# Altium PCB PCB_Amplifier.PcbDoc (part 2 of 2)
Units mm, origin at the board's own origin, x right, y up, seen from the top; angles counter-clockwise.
Board outline 88.51 x 102.08 mm, 4 copper layers (Top Layer, GND, VDD, Bottom Layer); 234 components, 166 nets, 733 pads, 363 vias.
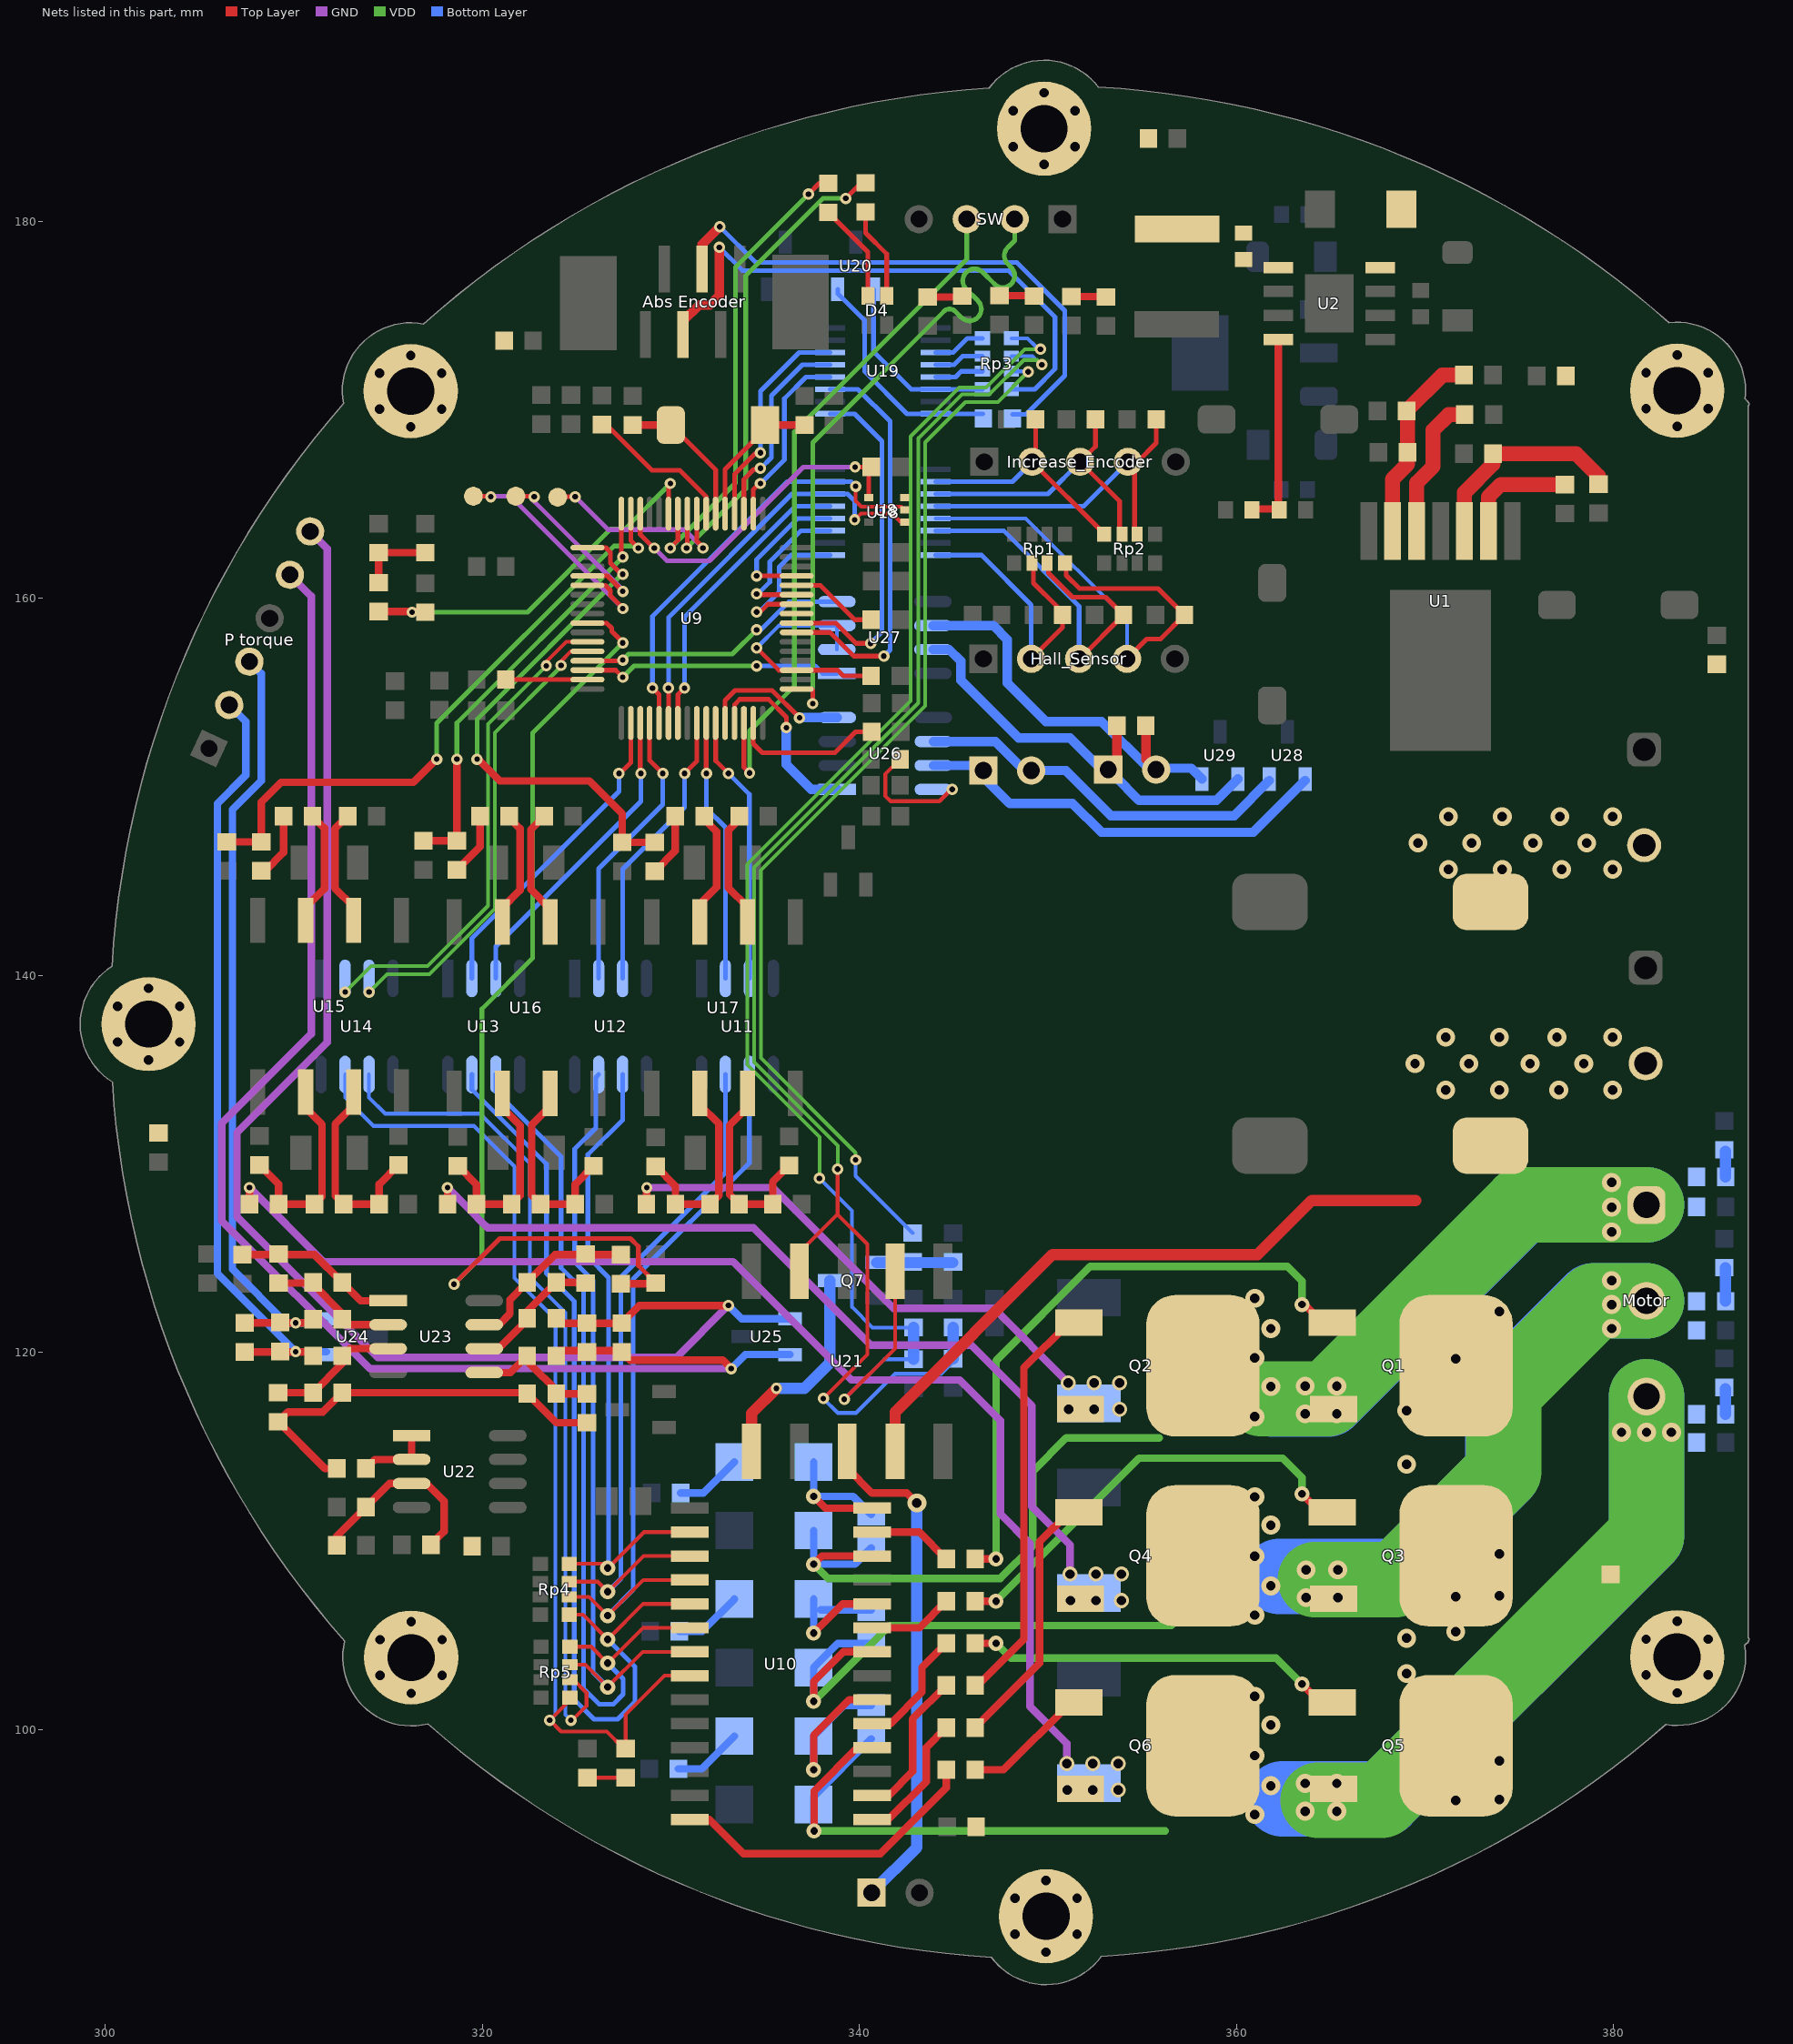
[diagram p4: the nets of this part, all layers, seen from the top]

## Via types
v1: diameter 0.6, hole 0.3, Top Layer to Bottom Layer, 150 vias
v2: diameter 1, hole 0.5, Top Layer to Bottom Layer, 134 vias
v3: diameter 0.8, hole 0.5, Top Layer to Bottom Layer, 60 vias
v4: diameter 0.8, hole 0.4, Top Layer to Bottom Layer, 19 vias

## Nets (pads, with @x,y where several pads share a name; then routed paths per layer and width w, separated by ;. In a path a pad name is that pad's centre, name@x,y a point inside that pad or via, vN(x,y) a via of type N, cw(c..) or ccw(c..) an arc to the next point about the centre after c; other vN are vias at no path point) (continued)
ADC12_IN15: C88.2 R99.2 U9.25 | length 55
  Top Layer w0.25: v1(318.5,123.625) 320.925,126.05 327.853,126.05 328.275,125.628 328.275,124.615 C88.2@329.2,123.69 ; U9.25@325.575,158.7 326.593,158.7 326.865,158.428 326.865,158.26 v1@327.325,157.8
  Top Layer w0.4: R99.2@327.35,123.655 C88.2@329.165,123.655
  VDD w0.25: v1(318.5,123.625) 319.975,125.1 319.975,138.225 322.675,140.925 322.675,152.871 v1(327.45,157.646)
ADC123_IN1: C35.2 R38.2 U9.15 | length 32.8
  Top Layer w0.25: U9.15@327.875,164.5 327.875,163.075 v1(328.275,162.675)
  Top Layer w0.4: C35.2@306.45,147.095 R38.2@308.275,147.095 308.275,149.2 309.325,150.25 316.35,150.25 v1@317.638,151.537
  VDD w0.25: v1(317.581,151.475) 317.581,153.381 326.985,162.785 328.165,162.785 v1(328.275,162.675)
ADC123_IN2: C45.2 R48.2 U9.16 | length 22.8
  Top Layer w0.25: U9.16@327.375,164.5 327.375,162.3 v1@327.475,162.2
  Top Layer w0.4: C45.2@316.875,147.145 R48.2@318.65,147.145 v1(318.65,151.475)
  VDD w0.25: v1(318.65,151.475) 318.65,153.4 v1(327.45,162.2)
ADC123_IN3: C55.2 R58.2 U9.17 | length 27.9
  Top Layer w0.25: U9.17@325.575,162.7 326.55,162.7 326.8,162.45 326.8,161.875 v1@327.45,161.225
  Top Layer w0.4: v1@319.775,151.475 320.925,150.325 325.675,150.325 327.425,148.575 C55.2@327.425,147.07 R58.2@329.15,147.07
  VDD w0.25: v1(319.719,151.475) 319.719,153.588 327.356,161.225 v1@327.45,161.225
  other v1: 327.45,161.289
ADC123_IN13: C79.2 R103.1 U9.11 | length 20.6
  Top Layer w0.25: U9.11@329.875,164.5 v1@329.875,166.1
  Top Layer w0.4: R103.1@314.5,159.305 C79.2@316.94,159.305
  VDD w0.25: v1(316.275,159.275) 322.4,159.275 326.8,163.675 327.55,163.675 v1(329.975,166.1)
BRAKE_INPUT_SIG: R71.1 Rp3.7 | length 56.9
  VDD w0.2: v1(339.8,130.225) 339.8,130.6 334.775,135.625 334.775,145.6 343.485,154.31 343.485,168.285 345.625,170.425 347.35,170.425 v1(348.95,172.025)
  Bottom Layer w0.2: v1(339.8,130.225) 339.8,129.37 R71.1@342.825,126.345 ; Rp3.7@348.07,172.05 v1@348.925,172.05 ; v1@348.95,172.05 v1@349.075,172.05
CLOSE_SIG: C151.2 R72.1 Rp3.6 U21.9 | length 81.7
  Top Layer w0.2: U21.9@336.815,124.325 336.815,125.315 338.825,127.325 ; v1(338.088,117.563) 340.425,119.9 340.425,125.75 338.838,127.337 ; 338.842,127.337 v1(338.842,129.733)
  VDD w0.2: v1@338.85,129.733 338.85,130.975 334.415,135.41 334.415,145.749 343.125,154.459 343.125,168.5 345.45,170.825 346.9,170.825 348.725,172.65 349.425,172.65 v1(349.675,172.4)
  Bottom Layer w0.2: v1(338.088,117.563) 338.85,116.8 339.825,116.8 341.9,118.875 344.33,118.875 C151.2@344.975,119.52 ; Rp3.6@348.07,172.85 349.175,172.85 v1@349.45,172.575
  Bottom Layer w0.6: C151.2@344.975,119.67 R72.1@344.975,121.33
D_GND: U8.3
DAC_OUT1: tp1.1 U9.20 | length 10.2
  Top Layer w0.25: tp1.1@321.912,165.425 v1@322.75,165.425 ; U9.20@325.575,161.2 326.625,161.2 327.35,160.475 v1@327.35,160.3
  GND w0.25: v1@322.75,165.425 322.75,165.15 327.45,160.45 v1@327.45,160.225
  other v1: 327.45,160.379 322.75,165.4
DAC_OUT2: tp2.1 U9.21 | length 13
  Top Layer w0.25: tp2.1@319.5,165.425 v1@320.45,165.425 ; U9.21@325.575,160.7 326.525,160.7 326.8,160.425 326.8,160.15 v1@327.45,159.5
  GND w0.25: v1@320.45,165.425 321.5,165.425 327.341,159.584 v1@327.341,159.359
  other v1: 327.45,159.468 320.45,165.4
DRIVE_H1: R20.1 U10.27 | length 4.5
  Top Layer w0.4: U10.27@340.675,110.48 343.175,110.48 R20.1@344.605,109.05
DRIVE_H2: R22.1 U10.23 | length 4.5
  Top Layer w0.4: U10.23@340.675,105.4 343.19,105.4 R22.1@344.605,106.815
DRIVE_H3: R24.1 U10.19 | length 6.5
  Top Layer w0.4: U10.19@340.675,100.32 341.645,100.32 343.325,102 343.325,103.3 R24.1@344.605,104.58
DRIVE_L1: R21.1 U10.16 | length 8
  Top Layer w0.4: U10.16@340.675,96.51 341.56,96.51 342.825,97.775 342.825,100.565 R21.1@344.605,102.345
DRIVE_L2: R23.1 U10.15 | length 7
  Top Layer w0.4: U10.15@340.675,95.24 341.54,95.24 343.55,97.25 343.55,99.055 R23.1@344.605,100.11
DRIVE_L3: R25.1 U10.14 | length 16.8
  Top Layer w0.4: U10.14@331,95.24 332.035,95.24 333.85,93.425 341.125,93.425 344.605,96.905 R25.1@344.605,97.875
EN: Rp5.2 U14.6 | length 44.6
  Top Layer w0.2: Rp5.2@324.645,102.65 324.838,102.65 325.525,101.963 325.525,101.25 324.775,100.5 v1(324.7,100.5)
  Bottom Layer w0.2: U14.6@313.99,134.75 313.99,133.535 314.85,132.675 319.875,132.675 322.525,130.025 322.525,124 324.4,122.125 324.4,100.8 v1(324.7,100.5)
FAULT: R60.2 Rp5.1 U10.8 U14.7 | length 54.1
  Top Layer w0.2: Rp5.1@324.645,101.57 v1(323.575,100.5) 324.175,99.9 326.6,99.9 327.505,98.995 R60.2@327.6,98.995 ; R60.2@327.6,99.27 327.6,100.8 329.66,102.86 U10.8@331,102.86
  Bottom Layer w0.2: U14.7@312.72,134.75 312.72,133.53 314.225,132.025 319.55,132.025 321.7,129.875 321.7,123.95 323.885,121.765 323.885,119.457 323.875,119.447 323.875,100.8 v1(323.575,100.5)
HIN1: Rp4.4 U10.2 U12.6 | length 34.6
  Top Layer w0.2: Rp4.4@324.62,108.8 326.425,108.8 v4(326.65,108.575) 326.675,108.575 328.58,110.48 U10.2@331,110.48
  Bottom Layer w0.25: v4@326.7,108.625 326.7,123.975 325.6,125.075 325.6,130.5 327.44,132.34 U12.6@327.44,134.75
HIN2: Rp4.3 U10.3 U11.7 | length 37.4
  Top Layer w0.2: Rp4.3@324.62,107.85 326.112,107.85 v4(326.65,107.313) 328.547,109.21 U10.3@331,109.21
  Bottom Layer w0.25: v4(326.65,107.313) 327.35,108.013 327.35,124 332.895,129.545 U11.7@332.895,134.75
HIN3: Rp4.2 U10.4 U11.6 | length 39.4
  Top Layer w0.2: Rp4.2@324.62,107.05 325.65,107.05 v4(326.65,106.05) 328.54,107.94 U10.4@331,107.94
  Bottom Layer w0.25: v4@326.638,106.063 328,107.425 328,123.9 334.165,130.065 U11.6@334.165,134.75
LIN1: Rp4.1 U10.5 U13.7 | length 51.1
  Top Layer w0.2: Rp4.1@324.62,106.1 325.337,106.1 v4(326.65,104.788) 328.532,106.67 U10.5@331,106.67
  Bottom Layer w0.25: U13.7@319.445,134.75 319.445,133.955 323.4,130 323.4,124.2 324.875,122.725 324.875,101.6 325.925,100.55 327.175,100.55 328.1,101.475 328.1,103.338 v4(326.65,104.788)
LIN2: Rp5.4 U10.6 U13.6 | length 46.7
  Top Layer w0.2: Rp5.4@324.645,104.4 325.775,104.4 v4(326.65,103.525) 328.525,105.4 U10.6@331,105.4
  Bottom Layer w0.25: U13.6@320.715,134.75 320.715,133.86 324.175,130.4 324.175,124.5 325.375,123.3 325.375,102.175 326.2,101.35 326.95,101.35 327.475,101.875 327.475,102.7 v4(326.65,103.525)
LIN3: Rp5.3 U10.7 U12.7 | length 41.4
  Top Layer w0.2: Rp5.3@324.645,103.45 325.462,103.45 v4(326.65,102.263) ; v4@326.65,102.275 328.505,104.13 U10.7@331,104.13
  Bottom Layer w0.25: U12.7@326.17,134.75 326.015,134.595 326.015,131.915 324.9,130.8 324.9,124.8 325.875,123.825 325.875,103.038 v4(326.65,102.263)
NetBrake_1: Brake.1 U21.3 | length 27
  Top Layer w0.4: U21.3@339.355,114.765 339.355,113.87 340.675,112.55 342.525,112.55 v2(343.05,112.025)
  Bottom Layer w0.6: Brake.1@340.65,91.35 343.05,93.75 v2(343.05,112.025)
NetC1_2: C1.2 U9.47 | length 8
  Top Layer w0.25: U9.47@334.375,153.4 334.375,152.3 334.85,151.825 338.7,151.825 339.8,152.925 C1.2@340.655,152.925
NetC2_2: C2.2 U9.31 | length 4.3
  Top Layer w0.25: C2.2@321.245,155.7 U9.31@325.575,155.7
NetC3_1: C3.1 U9.7 | length 8
  Top Layer w0.25: C3.1@326.35,169.23 326.57,169.23 329,166.8 330.475,166.8 331.875,165.4 U9.7@331.875,164.5
NetC4_1: C4.1 U9.6 Y1.1 | length 7.5
  Top Layer w0.25: Y1.1@330,169.2 332.375,166.825 U9.6@332.375,164.5
  Top Layer w0.4: C4.1@328.18,169.2 Y1.1@330,169.2
NetC5_1: C5.1 U9.5 Y1.2 | length 7.3
  Top Layer w0.2: C5.1@336.895,169.2 C5.1@336.9,169.205
  Top Layer w0.25: U9.5@332.875,164.5 332.875,166.85 Y1.2@335,168.975
  Top Layer w0.4: Y1.2@335,169.2 C5.1@336.895,169.2
NetC21_1: C21.1 D5.2 U10.28 | length 8.6
  Top Layer w0.4: v4(337.575,112.375) 338.2,111.75 U10.28@340.675,111.75
  Bottom Layer w0.4: D5.2@337.575,114.2 v4(337.575,112.375) 339.665,112.375 C21.1@340.625,111.415
NetC22_1: C22.1 D7.2 U10.24 | length 8.2
  Top Layer w0.4: v4(337.575,105.125) 339.12,106.67 U10.24@340.675,106.67
  Bottom Layer w0.4: v4(337.575,105.125) D7.2@337.575,106.93 ; D7.2@337.948,106.353 C22.1@340.625,106.353
NetC23_1: C23.1 D9.2 U10.20 | length 11.2
  Top Layer w0.4: v4(337.575,97.875) 337.575,99.7 339.465,101.59 U10.20@340.675,101.59
  Bottom Layer w0.4: v4(337.575,97.875) D9.2@337.575,99.66 339.205,101.29 C23.1@340.625,101.29
NetC31_1: C31.1 C32.2 R35.2 U15.3 | length 10.2
  Top Layer w0.4: U15.3@313.17,133.095 312.2,132.125 312.2,128.32 C31.1@312.645,127.875 R35.2@314.53,127.875 314.53,128.935 C32.2@315.55,129.955
NetC31_2: C31.2 C33.2 R34.2 U15.2 | length 10
  Top Layer w0.4: C33.2@308.175,129.955 309.195,128.935 R34.2@309.195,127.875 C31.2@311.105,127.875 311.5,128.27 311.5,132.1 U15.2@310.63,132.97
NetC41_1: C41.1 C42.2 R45.2 U16.3 | length 10
  Top Layer w0.4: U16.3@323.595,133.045 322.625,132.075 322.625,128.345 C41.1@323.095,127.875 R45.2@324.93,127.875 324.93,128.935 C42.2@325.9,129.905
NetC41_2: C41.2 C43.2 R44.2 U16.2 | length 10
  Top Layer w0.4: C43.2@318.7,129.905 319.695,128.91 R44.2@319.695,127.875 C41.2@321.555,127.875 322,128.32 322,132.05 U16.2@321.055,132.995
NetC51_1: C51.1 C52.2 R55.2 U17.3 | length 10
  Top Layer w0.4: U17.3@334.07,133.02 333.11,132.06 333.11,128.385 C51.1@333.62,127.875 R55.2@335.405,127.875 335.405,129.06 C52.2@336.275,129.93
NetC51_2: C51.2 C53.2 R54.2 U17.2 | length 10.2
  Top Layer w0.4: C53.2@329.2,129.88 330.245,128.835 R54.2@330.245,127.875 C51.2@332.08,127.875 332.55,128.345 332.55,132.125 U17.2@331.53,133.145
NetC62_2: C62.2 Hall_Sensor.2 Rp1.2 U18.16 | length 14.9
  Top Layer w0.25: Hall_Sensor.2@349.115,156.8 350.778,158.463 C62.2@350.778,159.125 ; Rp1.2@349.225,161.88 349.225,160.825 C62.2@350.478,159.572
  Bottom Layer w0.25: U18.16@344.05,162.3 346.475,162.3 349.115,159.66 Hall_Sensor.2@349.115,156.8
NetC63_2: C63.2 Hall_Sensor.3 Rp1.3 U18.14 | length 20.8
  Top Layer w0.25: Rp1.3@350.025,161.88 350.025,161.35 351.3,160.075 353.062,160.075 C63.2@354.012,159.125 351.687,156.8 Hall_Sensor.3@351.655,156.8
  Bottom Layer w0.25: U18.14@344.05,163.6 347.65,163.6 351.655,159.595 Hall_Sensor.3@351.655,156.8
NetC64_2: C64.2 Hall_Sensor.4 Rp1.4 U18.13 | length 26.3
  Top Layer w0.25: Rp1.4@350.975,161.88 350.975,161.225 351.675,160.525 355.845,160.525 C64.2@357.245,159.125 355.97,157.85 355.245,157.85 Hall_Sensor.4@354.195,156.8
  Bottom Layer w0.2: U18.13@344.05,164.25 348.825,164.25 354.195,158.88 Hall_Sensor.4@354.195,156.8
NetC65_2: C65.2 Increase_Encoder.2 Rp2.4 U18.10 | length 13
  Top Layer w0.25: Increase_Encoder.2@349.165,167.25 352.85,163.565 Rp2.4@352.85,163.42 ; Increase_Encoder.2@349.345,167.43 C65.2@349.345,169.5
  Bottom Layer w0.25: U18.10@344.05,166.2 348.115,166.2 Increase_Encoder.2@349.165,167.25
NetC66_2: C66.2 Increase_Encoder.3 Rp2.3 U18.11 | length 15.6
  Top Layer w0.25: C66.2@352.52,169.5 352.52,168.065 Increase_Encoder.3@351.705,167.25 353.8,165.155 Rp2.3@353.8,163.42
  Bottom Layer w0.25: U18.11@344.05,165.55 350.005,165.55 Increase_Encoder.3@351.705,167.25
NetC67_2: C67.2 Increase_Encoder.4 Rp2.2 U18.12 | length 17.3
  Top Layer w0.25: Rp2.2@354.6,163.42 Increase_Encoder.4@354.6,166.895 ; Increase_Encoder.4@354.75,167.25 355.745,168.245 C67.2@355.745,169.5
  Bottom Layer w0.25: U18.12@344.05,164.9 351.895,164.9 Increase_Encoder.4@354.245,167.25
NetC72_1: C72.1 L1.2 T1.2 U2.8
NetC72_2: C72.2 U2.1
NetC80_2: C80.2 R85.1 R86.2 U22.3 | length 10.3
  Top Layer w0.4: R86.2@312.28,109.775 312.28,110.26 R85.1@313.82,111.8 315.08,113.06 U22.3@316.25,113.06 317.04,113.06 317.975,112.125 317.975,110.505 C80.2@317.27,109.8
NetC82_2: C82.2 R90.2 R91.2 U23.3 | length 6.1
  Top Layer w0.4: C82.2@309.175,117.87 311.025,117.87 R91.2@311.03,117.875 R90.2@312.57,119.415 ; R90.2@312.955,120.21 U23.3@315,120.21
NetC83_1: C83.1 R89.2 R92.1 U23.2 | length 6.2
  Top Layer w0.4: C83.1@309.2,123.69 310.995,123.69 310.995,123.655 R89.2@312.57,122.08 ; R89.2@312.865,121.48 U23.2@315,121.48
NetC83_2: C83.2 R92.2 R93.1 U23.1 | length 8.7
  Top Layer w0.4: R93.1@307.275,125.195 311.1,125.195 R92.2@312.57,123.725 313.545,122.75 U23.1@315,122.75
NetC86_1: C86.1 R95.1 R96.1 U23.5 | length 6.8
  Top Layer w0.4: U23.5@320.1,118.94 321.495,118.94 R95.1@322.38,119.825 322.38,119.545 324.105,117.82 C86.1@325.55,117.82
NetC87_1: C87.1 R94.1 R97.1 U23.6 | length 7.1
  Top Layer w0.4: U23.6@320.1,120.21 320.86,120.21 322.38,121.73 R94.1@322.38,121.825 322.38,122.185 R97.1@323.92,123.725 325.44,123.725 C87.1@325.475,123.69
NetC87_2: C87.2 R97.2 R99.1 U23.7 | length 9.2
  Top Layer w0.4: U23.7@320.1,121.48 320.88,121.48 321.46,122.06 321.46,122.805 R97.2@322.38,123.725 323.85,125.195 R99.1@327.35,125.195
NetC91_2: C91.2 MH1.1
  other v3: 383.375,169.125 381.73,170.075 385.02,170.075 381.73,171.975 385.02,171.975 383.375,172.925
NetC92_2: C92.2 MH2.1
  other v3: 349.8,183.025 348.155,183.975 351.445,183.975 348.155,185.875 351.445,185.875 349.8,186.825
NetC93_2: C93.2 MH3.1
  other v3: 316.2,169.1 314.555,170.05 317.845,170.05 314.555,171.95 317.845,171.95 316.2,172.9
NetC94_2: C94.2 MH4.1
  other v3: 302.3,135.525 300.655,136.475 303.945,136.475 300.655,138.375 303.945,138.375 302.3,139.325
NetC95_2: C95.2 MH5.1
  other v3: 316.225,101.925 314.58,102.875 317.87,102.875 314.58,104.775 317.87,104.775 316.225,105.725
NetC96_2: C96.2 MH6.1
  other v3: 349.9,88.2 348.255,89.15 351.545,89.15 348.255,91.05 351.545,91.05 349.9,92
NetC97_2: C97.2 MH7.1
  other v3: 383.375,101.95 381.73,102.9 385.02,102.9 381.73,104.8 385.02,104.8 383.375,105.75
NetCff_1: Cff.1 Rfbb.2 Rfbt.1 U1.6 | length 10.5
  Top Layer w0.8: U1.6@368.285,163.575 368.285,166.335 369.07,167.12 Rfbt.1@369.07,167.75 369.07,170 370.92,171.85 Rfbb.2@372.07,171.85
NetCo1_1: Co1.1 R31.2 | length 1.4
  Bottom Layer w0.6: Co1.1@385.945,129.325 R31.2@385.945,130.685
NetCo3_1: Co3.1 R32.2 | length 1.8
  Bottom Layer w0.6: Co3.1@385.945,122.725 R32.2@385.945,124.5
NetCo5_1: Co5.1 R33.2 | length 1.3
  Bottom Layer w0.6: Co5.1@385.945,116.725 R33.2@385.945,118.075
NetCss_2: Css.2 U1.5 | length 7.7
  Top Layer w0.8: U1.5@369.555,163.575 369.555,166.13 370.425,167 370.425,168.925 371.25,169.75 Css.2@372.105,169.75
NetD1_A: D1.A R77.1 | length 1.8
  Top Layer w0.4: D1.A@351.247,176.02 R77.1@353.05,176.02
NetD2_A: D2.A R78.1 | length 1.8
  Top Layer w0.4: D2.A@347.436,176.07 R78.1@349.239,176.07
NetD3_A: D3.A R79.1 | length 1.8
  Top Layer w0.4: D3.A@343.625,175.995 R79.1@345.403,175.995
NetD4_1: D4.1 R100.1 | length 4.9
  Top Layer w0.25: R100.1@340.325,180.505 340.325,179.4 341.45,178.275 D4.1@341.45,176.05
NetD4_2: D4.2 R104.1 | length 5.3
  Top Layer w0.25: R104.1@338.35,180.48 340.45,178.38 D4.2@340.45,176.05
NetD5_1: D5.1 R12.2 | length 3.5
  Bottom Layer w0.4: R12.2@330.52,112.55 331.725,112.55 D5.1@333.375,114.2
NetD7_1: D7.1 R13.2 | length 3.6
  Bottom Layer w0.4: R13.2@330.445,105.225 331.67,105.225 D7.1@333.375,106.93
NetD9_1: D9.1 R14.2 | length 3.7
  Bottom Layer w0.4: R14.2@330.395,97.925 331.64,97.925 D9.1@333.375,99.66
NetD11_K: D11.K R60.1 | length 2
  Top Layer w0.2: D11.K@325.575,97.455 R60.1@327.6,97.455
NetP485_1: P485.1 R4.1 U27.7 U29.1 | length 22.4
  Top Layer w0.5: P485.1@353.655,151.38 R4.1@353.655,153.25
  Bottom Layer w0.5: U27.7@343.9,157.295 344.755,157.295 345.375,156.675 345.375,155.675 348.45,152.6 351.175,152.6 353.2,150.575 353.55,150.575 354.825,149.3 358.95,149.3 U29.1@360.075,150.425
NetP485_2: P485.2 R4.2 U27.6 U29.2 | length 21.5
  Top Layer w0.5: R4.2@355.195,153.25 355.195,151.47 P485.2@355.74,150.925
  Bottom Layer w0.5: U27.6@343.9,158.565 347.11,158.565 347.85,157.825 347.85,155.525 349.9,153.475 352.84,153.475 355.315,151 357.6,151 U29.2@358.175,150.425
NetPcan_1: Pcan.1 U26.7 U28.1 | length 22.3
  Bottom Layer w0.5: U26.7@343.925,151.145 345.955,151.145 346.575,150.525 347.975,149.125 351.305,149.125 352.83,147.6 360.9,147.6 U28.1@363.65,150.35
NetPcan_2: Pcan.2 U26.6 U28.2 | length 20.2
  Bottom Layer w0.5: U26.6@343.925,152.415 347.225,152.415 348.765,150.875 350.95,150.875 353.35,148.475 359.875,148.475 U28.2@361.75,150.35
NetQ1_1: Q1.1 R20.2 | length 33.4
  Top Layer w0.4: R20.2@346.145,109.05 v4(347.25,109.05) ; v4@363.6,122.55 364.55,121.6 Q1.1@365.075,121.6
  VDD w0.4: v4(347.25,109.05) 347.25,119.575 352.25,124.575 362.7,124.575 363.475,123.8 v4(363.475,122.55)
NetQ2_1: Q2.1 R21.2 | length 21.4
  Top Layer w0.4: R21.2@346.145,102.345 346.27,102.345 348.725,104.8 348.725,119.2 Q2.1@351.125,121.6
NetQ3_1: Q3.1 R22.2 | length 23.8
  Top Layer w0.4: R22.2@346.145,106.815 v4(347.25,106.815) ; v4@363.5,112.5 364.475,111.525 Q3.1@365.075,111.525
  VDD w0.4: v4(347.25,106.815) 354.835,114.4 362.45,114.4 363.475,113.375 v4(363.475,112.5)
NetQ4_1: Q4.1 R23.2 | length 13.5
  Top Layer w0.4: R23.2@346.145,100.11 349.55,103.515 349.55,109.95 Q4.1@351.125,111.525
NetQ5_1: Q5.1 R24.2 | length 20.3
  Top Layer w0.4: R24.2@346.145,104.58 v4(347.25,104.58) v4@347.305,104.58 ; v4(363.475,102.425) 364.45,101.45 Q5.1@365.075,101.45
  VDD w0.4: v4(347.25,104.58) 348.03,103.8 362.1,103.8 v4(363.475,102.425)
NetQ6_1: Q6.1 R25.2 | length 6.6
  Top Layer w0.4: R25.2@346.145,97.875 347.65,97.875 Q6.1@351.225,101.45
NetQ7_1: Q7.1 R70.1 R71.2 | length 4
  Bottom Layer w0.6: Q7.1@340.925,124.775 R70.1@344.945,124.775
NetQ7_3: Q7.3 U21.1 | length 11.6
  Top Layer w0.6: U21.1@334.275,114.765 334.275,116.775 v1(335.6,118.1)
  Bottom Layer w0.6: v1(335.6,118.1) 337.075,118.1 338.425,119.45 Q7.3@338.425,123.825
NetR1_2: R1.2 U9.60 | length 4.8
  Top Layer w0.25: U9.60@336.675,160.7 337.925,160.7 339.75,158.875 R1.2@340.68,158.875
NetR5_1: R5.1 U26.8 | length 6.3
  Top Layer w0.2: R5.1@342.16,151.475 341.375,150.69 341.375,149.525 341.65,149.25 344.25,149.25 344.925,149.925 v1(344.925,149.875)
NetR36_1: R36.1 U15.7 | length 5.5
  Top Layer w0.4: U15.7@310.63,143.605 311.625,144.6 311.625,147.82 R36.1@310.995,148.45
NetR36_2: R36.2 R38.1 | length 3.5
  Top Layer w0.4: R38.1@308.275,145.555 308.48,145.555 309.455,146.53 R36.2@309.455,148.45
NetR37_1: R37.1 U15.6 | length 5.5
  Top Layer w0.4: R37.1@312.855,148.45 312.185,147.78 312.185,144.64 U15.6@313.17,143.655
NetR46_1: R46.1 U16.7 | length 5.5
  Top Layer w0.4: U16.7@321.055,143.58 322,144.525 322,147.8 321.42,148.38 R46.1@321.42,148.45
NetR46_2: R46.2 R48.1 | length 3.4
  Top Layer w0.4: R48.1@318.65,145.605 319.88,146.835 R46.2@319.88,148.45
NetR47_1: R47.1 U16.6 | length 5.6
  Top Layer w0.4: R47.1@323.28,148.45 322.575,147.745 322.575,144.575 U16.6@323.595,143.555
NetR56_1: R56.1 U17.7 | length 5.3
  Top Layer w0.4: U17.7@331.53,143.78 332.425,144.675 332.425,147.65 331.77,148.305 R56.1@331.77,148.45
NetR56_2: R56.2 R58.1 | length 3.4
  Top Layer w0.4: R58.1@329.15,145.53 330.23,146.61 R56.2@330.23,148.45
NetR57_1: R57.1 U17.6 | length 5.5
  Top Layer w0.4: R57.1@333.63,148.45 333.63,148.28 333.05,147.7 333.05,144.65 U17.6@334.07,143.63
NetR75_1: R75.1 R76.2 U2.4 | length 10.3
  Top Layer w0.4: R75.1@360.875,164.75 362.225,164.75 U2.4@362.225,173.745
NetR81_1: R81.1 U19.16 U20.2 | length 12.2
  Bottom Layer w0.25: U20.2@338.85,176.4 338.85,176.175 340.275,174.75 340.275,172.05 342.525,169.8 U19.16@344.05,169.8 R81.1@346.555,169.8
NetR87_1: R87.1 U22.1 U22.2 | length 3.9
  Top Layer w0.4: R87.1@313.82,113.85 314.3,114.33 U22.2@316.25,114.33 U22.1@316.25,115.6
NetR100_2: R100.2 U9.9 | length 26
  Top Layer w0.25: v1@330.875,162.675 U9.9@330.875,164.5 ; v1(339.275,181.225) 340.095,182.045 R100.2@340.325,182.045
  VDD w0.25: v1(330.837,162.675) 333.975,165.812 333.975,177.125 338.075,181.225 v1(339.275,181.225)
NetR101_1: R101.1 R102.2 R103.2 | length 4.1
  Top Layer w0.4: R103.2@314.5,160.845 R101.1@314.5,162.43 R102.2@316.975,162.43
NetR104_2: R104.2 U9.10 | length 25.1
  Top Layer w0.25: v1@329.975,162.7 330.375,163.1 U9.10@330.375,164.5 ; v1(337.3,181.45) 337.87,182.02 R104.2@338.35,182.02
  VDD w0.25: v1(329.975,162.675) 333.425,166.125 333.425,177.575 v1(337.3,181.45)
NetRenb_2: Renb.2 Rent.2 U1.3 | length 11.2
  Top Layer w0.8: U1.3@372.095,163.575 372.095,165.62 373.61,167.135 Renb.2@373.61,167.675 378.025,167.675 379.2,166.5 Rent.2@379.2,166.07
NetRon_2: Ron.2 U1.2 | length 6.1
  Top Layer w0.8: U1.2@373.365,163.575 373.365,165.39 374.02,166.045 Ron.2@377.425,166.045
NetRp3_1: Rp3.1 U19.14 U20.1 | length 9.9
  Bottom Layer w0.25: U20.1@340.75,176.4 340.75,173.1 342.75,171.1 U19.14@344.05,171.1 Rp3.1@346.53,171.1
NetRp3_2: Rp3.2 U19.13 | length 2.6
  Bottom Layer w0.25: U19.13@344.05,171.75 345.1,171.75 345.4,172.05 Rp3.2@346.53,172.05
NetRp3_3: Rp3.3 U19.12 | length 2.7
  Bottom Layer w0.25: U19.12@344.05,172.4 345.025,172.4 345.475,172.85 Rp3.3@346.53,172.85
NetRp3_4: Rp3.4 U19.11 | length 2.8
  Bottom Layer w0.25: U19.11@344.05,173.05 344.975,173.05 345.725,173.8 Rp3.4@346.53,173.8
Nettp3_1: tp3.1 U9.8 | length 10.6
  Top Layer w0.25: tp3.1@324.112,165.4 v1(324.925,165.4) ; U9.8@331.375,164.5 331.375,163.05 v1@331.7,162.725
  GND w0.25: v1(324.925,165.4) 326.675,163.65 330.725,163.65 v1(331.7,162.675)
NetU9_2: U9.2 U19.4 | length 9.7
  Top Layer w0.25: U9.2@334.375,164.5 334.375,165.775 v1@334.725,166.125
  Bottom Layer w0.25: v1(334.75,166.1) 334.765,166.1 336.025,167.36 336.025,170.6 337.175,171.75 U19.4@338.45,171.75
NetU9_3: U9.3 U19.5 | length 10.7
  Top Layer w0.25: U9.3@333.875,164.5 333.875,166.325 334.4,166.85 v1@334.625,166.85
  Bottom Layer w0.25: v1(334.75,166.913) 334.765,166.913 335.335,167.483 335.335,170.76 336.975,172.4 U19.5@338.45,172.4
NetU9_4: U9.4 U19.6 | length 11.7
  Top Layer w0.25: U9.4@333.375,164.5 333.375,166.6 334.45,167.675 v1@334.725,167.675
  Bottom Layer w0.25: v1(334.75,167.725) 334.75,171 336.8,173.05 U19.6@338.45,173.05
NetU9_27: U9.27 U14.2 | length 26.4
  Top Layer w0.2: v1@323.492,156.433 v1(323.391,156.433) 323.391,156.641 324.45,157.7 U9.27@325.575,157.7
  VDD w0.2: v1(312.725,139.125) 314.1,140.5 317.1,140.5 320.3,143.7 320.3,153.342 v1(323.391,156.433)
NetU9_28: U9.28 U14.3 | length 24.7
  Top Layer w0.2: v1(324.175,156.45) 324.175,156.675 324.7,157.2 U9.28@325.575,157.2
  VDD w0.2: v1(314,139.125) 314.95,140.075 317.184,140.075 320.66,143.551 320.66,152.875 324.175,156.39 v1(324.175,156.45)
NetU9_44: U9.44 U26.4 | length 8
  Top Layer w0.25: U9.44@332.875,153.4 332.875,154.6 333.4,155.125 335.375,155.125 v1(336.825,153.675)
  Bottom Layer w0.5: v1@336.835,153.685 U26.4@338.825,153.685
NetU9_45: U9.45 U26.1 | length 10
  Top Layer w0.25: U9.45@333.375,153.4 333.375,154.365 333.66,154.65 335.175,154.65 336.125,153.7 v1(336.125,153.15)
  Bottom Layer w0.5: v1(336.125,153.15) 336.125,151.2 337.45,149.875 U26.1@338.825,149.875
OPEN_SIG: C152.2 R73.1 Rp3.5 U21.7 | length 80.2
  Top Layer w0.2: v1(339.2,117.525) 341.895,120.22 U21.7@341.895,124.325
  VDD w0.2: v1(337.883,129.242) 337.883,131.433 334.055,135.261 334.055,145.898 342.72,154.563 342.72,168.594 342.715,168.599 345.301,171.185 346.725,171.185 348.765,173.225 v1(349.6,173.225)
  Bottom Layer w0.2: v1(337.883,129.242) 339.6,127.525 339.6,122.425 340.695,121.33 R73.1@342.875,121.33 ; v1(339.2,117.525) 341.32,119.645 C152.2@342.875,119.645 ; Rp3.5@348.07,173.8 348.925,173.8 v1@349.35,173.375
  Bottom Layer w0.6: C152.2@342.875,119.645 R73.1@342.875,121.33
REF_165: C82.1 C86.2 R87.2 R91.1 R96.2 | length 21.8
  Top Layer w0.4: R87.2@312.28,113.85 311.655,113.85 C82.1@309.175,116.33 309.695,116.85 311.545,116.85 R91.1@312.57,117.875 322.33,117.875 R96.2@322.38,117.825 323.925,116.28 C86.2@325.55,116.28
RS485_SIG: R3.1 U9.51 U27.2 U27.3 | length 13
  Top Layer w0.25: v1(334.55,157.38) 335.73,156.2 U9.51@336.675,156.2 338.85,156.2 339.15,155.9 340.7,155.9 R3.1@340.85,155.75
  Bottom Layer w0.2: v1(334.55,157.38) 335.735,158.565 U27.3@338.8,158.565 U27.2@338.8,157.295
SEN_1_RAW: Q2.3 R26.2 R54.1 | length 27.5
  Top Layer w0.4: R54.1@328.705,127.875 v1@328.705,128.73
  GND w0.4: v1(328.725,128.75) 335.4,128.75 341.8,122.35 347.125,122.35 v3(351.075,118.4)
  other v3: 351.1,117 352.45,117 353.8,117 352.45,118.4 353.8,118.4
SEN_2_RAW: Q4.3 R27.2 R44.1 | length 46.4
  Top Layer w0.4: R44.1@318.155,127.875 v1@318.155,128.745
  GND w0.4: v1(318.15,128.75) 319.337,127.563 319.426,127.474 319.992,126.908 320.275,126.625 334.375,126.625 340.6,120.4 345.925,120.4 349.15,117.175 349.15,111.825 351.175,109.8 v3(351.175,108.25)
  other v3: 351.2,106.85 352.55,106.85 353.9,106.85 352.55,108.25 353.9,108.25
SEN_3_RAW: Q6.3 R28.2 R34.1 | length 65.5
  Top Layer w0.4: R34.1@307.655,127.875 v1@307.655,128.745
  GND w0.4: v1(307.65,128.75) 311.575,124.825 333.3,124.825 339.575,118.55 345.325,118.55 347.475,116.4 347.475,111.45 349.05,109.875 349.05,101.225 351,99.275 v3(351,98.2)
  other v3: 351.025,96.8 352.375,96.8 353.725,96.8 352.375,98.2 353.725,98.2
SIG_1_+: "P torque.2" C81.1 R88.1 R90.1 U24.1 | length 42.2
  Top Layer w0.4: C81.1@307.4,120.035 R90.1@310.95,120.035
  Bottom Layer w0.4: 306.573,154.352 307.45,153.475 307.45,150.625 305.95,149.125 305.95,124.2 v1(310.1,120.05) U24.1@311.725,120.05
SIG_1_-: "P torque.3" C81.2 R88.2 R89.1 U24.2 | length 42.6
  Top Layer w0.4: C81.2@307.4,121.575 v1(310.1,121.575) R89.1@310.75,121.575
  Bottom Layer w0.4: 307.647,156.654 308.275,156.026 308.275,150.325 306.75,148.8 306.75,124.425 309.6,121.575 v1(310.1,121.575) U24.2@311.65,121.575
SIG_2_+: "P torque.5" C85.1 R95.2 R98.1 U25.2 | length 79.8
  Top Layer w0.4: R95.2@324.095,120.1 C85.1@327.37,120.1 ; C85.1@327.4,120.03 327.83,119.6 332.75,119.6 v1(333.2,119.15)
  GND w0.4: 309.794,161.258 310.925,160.127 310.925,136.9 306.175,132.15 306.175,127 314.025,119.15 v1(333.2,119.15)
  Bottom Layer w0.4: v1(333.2,119.15) 333.95,119.9 U25.2@336.325,119.9
SIG_2_-: "P torque.6" C85.2 R94.2 R98.2 U25.1 | length 81.8
  Top Layer w0.4: R94.2@323.92,121.55 C85.2@327.145,121.55 ; C85.2@327.4,121.57 328.33,122.5 v1(333.05,122.5)
  GND w0.4: 310.867,163.56 311.775,162.652 311.775,136.45 306.99,131.665 306.99,127.21 314.46,119.74 330.29,119.74 v1(333.05,122.5)
  Bottom Layer w0.4: v1(333.05,122.5) 333.75,121.8 U25.1@336.325,121.8
SPI1_CLK: U9.55 U19.3 | length 21.6
  Top Layer w0.25: U9.55@336.675,158.2 338.45,158.2 339.7,156.95 v1(341.3,156.95)
  Bottom Layer w0.25: U19.3@338.45,171.1 339.925,171.1 341.625,169.4 341.625,157.275 v1(341.3,156.95)
SPI1_MISO: U9.56 U19.1 | length 18.7
  Top Layer w0.25: U9.56@336.675,158.7 338.75,158.7 339.825,157.625 v1(340.6,157.625)
  Bottom Layer w0.25: U19.1@338.45,169.8 339.75,169.8 341.2,168.35 341.2,158.225 v1(340.6,157.625)
SPI1_MOSI: U9.57
SSI_CLK: "Abs Encoder.4" Rp3.8 | length 30.6
  Top Layer w0.5: 330.65,174 330.65,174.725 331.5,175.575 332.075,175.575 332.575,176.075 v1(332.575,178.625)
  Bottom Layer w0.25: v1(332.575,178.625) 333.8,177.4 347.9,177.4 350.375,174.925 350.375,172.175 349.3,171.1 Rp3.8@348.07,171.1
SSI_DATA: "Abs Encoder.3" R81.2 | length 29.9
  Top Layer w0.5: 331.65,177.475 331.65,178.775 v1(332.6,179.725)
  Bottom Layer w0.25: v1(332.6,179.725) 334.5,177.825 348.35,177.825 350.9,175.275 350.9,171.825 348.85,169.775 R81.2@348.12,169.775
SWCLK: SW.2 U9.49 | length 36.9
  Top Layer w0.25: U9.49@336.675,155.2 337.475,155.2 337.525,155.15 v1(337.525,154.425)
  VDD w0.25: v1(337.525,154.425) 337.525,168.275 344.488,175.238 cw(c344.781,174.944) 345.075,175.238 345.399,174.914 ccw(c345.841,175.355) 346.283,174.914 ccw(c345.841,175.355) 346.283,175.797 345.665,176.415 cw(c346.107,176.857) 345.665,177.299 cw(c346.107,176.857) 346.549,177.299 347.167,176.681 ccw(c347.609,177.123) 348.051,176.681 ccw(c347.609,177.123) 348.051,177.565 347.875,177.741 cw(c348.317,178.183) 347.875,178.625 348.235,178.985 SW.2@348.235,180.125
SWDIO: SW.3 U9.46 | length 36.9
  Top Layer w0.25: U9.46@333.875,153.4 333.875,151.05 v1(334.175,150.75)
  VDD w0.25: v1(334.175,150.75) 334.175,152.975 336.55,155.35 336.55,168.85 345.695,177.995 SW.3@345.695,180.125
TIM1_CH1: U9.41 U12.3 | length 15.2
  Top Layer w0.25: v1(330.73,150.725) 331.375,151.37 U9.41@331.375,153.4
  Bottom Layer w0.25: U12.3@327.44,139.85 327.44,145.64 330.73,148.93 v1(330.73,150.725)
TIM1_CH1N: U9.34 U13.2 | length 17.1
  Top Layer w0.25: v1@327.275,150.7 327.875,151.3 U9.34@327.875,153.4
  Bottom Layer w0.25: U13.2@319.445,139.85 319.445,141.97 327.25,149.775 v1(327.25,150.725)
TIM1_CH2: U9.42 U11.2 | length 13.9
  Top Layer w0.25: v1@331.875,150.775 U9.42@331.875,153.4
  Bottom Layer w0.25: v1(331.89,150.725) 331.89,148.86 332.895,147.855 U11.2@332.895,139.85
TIM1_CH2N: U9.35 U13.3 | length 16.7
  Top Layer w0.25: v1@328.375,150.8 U9.35@328.375,153.4
  Bottom Layer w0.25: U13.3@320.715,139.85 320.715,141.54 328.41,149.235 v1(328.41,150.725)
TIM1_CH3: U9.43 U11.3 | length 14.3
  Top Layer w0.25: U9.43@332.375,153.4 332.375,151.4 v1(333.05,150.725)
  Bottom Layer w0.25: v1(333.05,150.725) 334.165,149.61 U11.3@334.165,139.85
TIM1_CH3N: U9.36 U12.2 | length 15.2
  Top Layer w0.25: U9.36@328.875,153.4 328.875,151.42 v1(329.57,150.725)
  Bottom Layer w0.25: U12.2@326.17,139.85 326.17,145.67 329.57,149.07 v1(329.57,150.725)
TIM3_CH1: U8.2 U9.37 U18.7 | length 23.2
  Top Layer w0.2: v1(339.8,165.95) 339.8,165.175 340.1,164.875 342.225,164.875 U8.2@342.4,164.7
  Top Layer w0.25: v1(329.025,155.25) 329.375,154.9 U9.37@329.375,153.4
  Bottom Layer w0.25: v1(329.025,155.25) 329.025,159.05 336.175,166.2 U18.7@338.45,166.2 339.55,166.2 v1(339.8,165.95)
TIM3_CH2: U8.1 U9.38 U18.6 | length 22.3
  Top Layer w0.2: v1(339.75,164.175) 340.085,164.51 341.737,164.51 342.197,164.05 U8.1@342.4,164.05
  Top Layer w0.25: U9.38@329.875,153.4 v1(329.875,155.25)
  Bottom Layer w0.25: v1(329.875,155.25) 329.875,159 336.425,165.55 U18.6@338.45,165.55 339.373,165.55 339.558,165.365 339.56,165.365 339.75,165.175 v1(339.75,164.175)
TIM3_CH3: U9.39 U18.5 | length 15.9
  Top Layer w0.25: U9.39@330.375,153.4 330.375,154.9 v1(330.725,155.25)
  Bottom Layer w0.25: v1(330.725,155.25) 330.725,159.025 336.6,164.9 U18.5@338.45,164.9
TIM4_CH1: U9.58 U18.1 | length 8.3
  Top Layer w0.25: v1@334.6,159.15 335.15,159.7 U9.58@336.675,159.7
  Bottom Layer w0.25: v1@334.55,159.15 335.75,160.35 335.75,161.675 336.375,162.3 U18.1@338.45,162.3
  other v1: 334.55,159.29
TIM4_CH2: U9.59 U18.3 | length 8.1
  Top Layer w0.25: v1@334.55,160.2 U9.59@336.675,160.2
  Bottom Layer w0.25: v1@334.55,160.175 335.25,160.875 335.25,161.95 336.9,163.6 U18.3@338.45,163.6
  other v1: 334.55,160.245
TIM4_CH3: U9.61 U18.4 | length 7.8
  Top Layer w0.25: v1@334.575,161.2 U9.61@336.675,161.2
  Bottom Layer w0.25: v1(334.55,161.2) 334.55,162.075 336.725,164.25 U18.4@338.45,164.25
TIM5_CH1: R2.2 U8.4 U9.14 | length 17.5
  Top Layer w0.25: U9.14@328.375,164.5 328.375,163.4 328.515,163.26 328.517,163.26 328.86,162.917 328.86,162.915 329.1,162.675 v1(329.125,162.675) ; v1(339.775,166.975) R2.2@340.63,166.975 ; U8.4@340.5,165.35 R2.2@340.5,166.845
  GND w0.25: v1(329.125,162.675) 329.8,162 332.05,162 337.025,166.975 v1(339.775,166.975)
U_COIL: C21.2 Co1.2 Co2.2 D6.2 Motor.1 Q1.3 Q2.2 U10.26 | length 81.3
  Top Layer w0.4: v4(337.575,108.775) 338.01,109.21 U10.26@340.675,109.21
  VDD w0.4: v4(337.575,108.775) 338.325,108.025 347.475,108.025 349.2,109.75 349.2,113.7 350.975,115.475 355.9,115.475
  VDD w4: 361.325,117.55 364.825,117.55 375.105,127.83 Motor.1@381.75,127.83
  Bottom Layer w0.4: D6.2@337.575,110.565 v4(337.575,108.775) 339.765,108.775 C21.2@340.625,109.635
  Bottom Layer w4: 361.925,117.525 364.85,117.525 375.155,127.83 Motor.1@381.75,127.83
  other v2: 360.975,116.6 363.65,116.75 365.325,116.75 361.825,118.2 363.65,118.225 365.325,118.225 360.975,119.725 361.825,121.275 360.975,122.875 379.9,126.4 379.9,127.713 379.9,129.025
USART3_RX: U9.30 U27.1 | length 13.7
  Top Layer w0.25: U9.30@325.575,156.2 327.075,156.2 v1(327.45,155.825)
  VDD w0.25: v1(327.45,155.825) 328.05,156.425 v1(334.55,156.425)
  Bottom Layer w0.25: v1@334.6,156.425 337.65,156.425 338.05,156.025 U27.1@338.8,156.025
USART3_TX: U9.29 U27.4 | length 14.1
  Top Layer w0.25: U9.29@325.575,156.7 327.125,156.7
  VDD w0.25: v1(327.45,156.736) 327.764,157.05 333.265,157.05 v1(334.55,158.335)
  Bottom Layer w0.25: v1@334.7,158.275 336.26,159.835 U27.4@338.8,159.835
V_COIL: C22.2 Co3.2 Co4.2 D8.2 Motor.2 Q3.3 Q4.2 U10.22 | length 85.1
  Top Layer w0.4: v4(337.575,101.5) 337.575,102.55 339.155,104.13 U10.22@340.675,104.13
  VDD w0.4: v4(337.575,101.5) 341.6,105.525 356.55,105.525
  VDD w4: 364.175,107.95 368.425,107.95 374.175,113.7 374.175,117.925 379,122.75 Motor.2@381.75,122.75
  Bottom Layer w0.4: v4(337.575,101.5) D8.2@337.575,103.295 338.853,104.572 C22.2@340.625,104.572
  Bottom Layer w4: 362.275,108.125 368.625,108.125 374.125,113.625 374.125,117.95 378.925,122.75 Motor.2@381.75,122.75
  other v2: 360.975,106.075 363.7,107 365.375,107 361.825,107.625 363.7,108.475 365.375,108.475 360.975,109.2 361.825,110.85 360.975,112.35 379.9,121.275 379.9,122.55 379.9,123.825
VIN: Cin.2 FE4.1 R101.2 Rent.1 Ron.1 U1.1 | length 84.4
  Top Layer w0.4: R101.2@314.5,163.97 v1(314.5,165.4)
  GND w0.4: v1@314.775,165.4 316.375,165.4 333.55,182.575 347.025,182.575 347.95,181.65 351.825,181.65 352.95,182.775 364.325,182.775 381.275,165.825 v1(381.275,164.375)
VIN: Cin1.1 Cin2.1 FE4.2 Q1.2 Q3.2 Q5.2 U21.4 Vin_I.2 Vin_II.2 | length 34.3
  Top Layer w0.6: U21.4@341.895,114.765 341.895,116.845 350.25,125.2 361.125,125.2 364,128.075 369.5,128.075
  other v2: 371.625,96.25 373.95,96.3 373.95,98.35 369.025,102.975 369.025,104.85 371.625,105.2 371.625,107.05 373.95,107.1 373.95,109.325 369.025,114.075 369.025,116.925 371.625,119.675 373.95,122.175 371.1,133.925 373.95,133.925 377.1,133.925 379.95,133.925 369.475,135.325 372.325,135.325 375.575,135.325 378.425,135.325 371.1,136.725 373.95,136.725 377,136.725 379.95,136.725 371.25,145.625 374.1,145.625 377.25,145.625 379.95,145.625 369.625,147.025 372.475,147.025 375.725,147.025 378.575,147.025 371.25,148.425 374.1,148.425 377.15,148.425 379.95,148.425
W_COIL: C23.2 Co5.2 Co6.2 D10.2 Motor.3 Q5.3 Q6.2 U10.18 | length 94
  Top Layer w0.4: v4(337.6,94.625) 337.6,96.75 339.9,99.05 U10.18@340.675,99.05
  VDD w0.4: v4(337.6,94.625) 356.225,94.625
  VDD w4: 364.325,96.25 367.7,96.25 381.75,110.3 Motor.3@381.75,117.67
  Bottom Layer w0.4: v4(337.6,94.625) 337.575,94.65 D10.2@337.575,96.025 337.575,96.46 C23.2@340.625,99.51
  Bottom Layer w4: 362.45,96.325 367.8,96.325 381.75,110.275 Motor.3@381.75,117.67
  other v2: 360.975,95.5 363.65,95.675 365.325,95.675 361.825,97.025 363.65,97.15 365.325,97.15 360.975,98.625 361.825,100.25 360.975,101.775 380.425,115.775 381.75,115.775 383.075,115.775
pads on no net: "Abs Encoder.2" "Abs Encoder.5" Rp1.1 Rp1.8 Rp2.1 Rp2.8 U2.2 U2.3 U2.5 U9.33 U9.40 U9.50 U9.52 U9.53 U9.54 U9.62 U10.9 U10.10 U10.11 U10.17 U10.21 U10.25 U19.7 U19.10 U21.5 U21.6 U22.5 U22.6 U22.7 U26.5

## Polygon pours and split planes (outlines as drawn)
NetC97_2 on Top Layer "top_hole_7" (solid, remove dead copper, pour order 27): 378.375,95 378.375,108.125 378.925,108.675 379.175,108.925 389.275,108.925 389.275,101.6 390.375,100.5
NetC96_2 on Top Layer "top_hole_6" (solid, remove dead copper, pour order 25): 340.8,87.2 340.8,87.35 345.85,92.4 345.8,92.45 345.8,96.025 349.6,96.025 351.75,93.875 352.65,92.975 357.775,92.975 358.675,92.975 363.175,88.475 358.375,83.675 347.775,83.675
NetC95_2 on Top Layer "top_hole_5" (solid, remove dead copper, pour order 19): 307.55,109.075 308.475,110 308.6,110 319.825,110 320.125,109.7 322.375,107.45 322.375,99.7 322.375,98.65 319.6,95.875 318.4,97.075 307.125,97.075
NetC94_2 on Top Layer "top_hole_4" (solid, remove dead copper, pour order 17): 296.55,144.603 296.725,144.775 304.425,144.775 304.475,144.775 305.8,143.476 306.2,143.084 306.2,132.2 306.1,132.2 304.975,131.097 304.8,130.925 298.875,130.925 298.675,130.925 294.9,134.627
NetC93_2 on Top Layer "top_hole_3" (solid, remove dead copper, pour order 12): 321.575,178.9 321.55,178.875 321.55,170.875 315.975,165.3 315.875,165.2 309.6,165.2 308.25,165.2 306.5,166.95 310.55,171 310.55,176.05
NetC92_2 on Top Layer "top_hole_2" (solid, remove dead copper, pour order 10): 343,187.85 342.95,187.8 342.95,183.45 345.725,183.45 345.75,183.425 347.525,181.65 351.45,181.65 351.475,181.675 353.85,181.675 354.225,181.675 355.325,182.775 355.95,183.4 355.95,187.4 352.325,191.025
NetC91_2 on Top Layer "top_hole_1" (solid, remove dead copper, pour order 4): 376.925,179.95 376.9,179.925 376.9,170.075 376.9,169.8 378.475,168.225 380.375,166.325 387.875,166.325 387.875,175.25 384.875,178.25
NetC97_2 on Bottom Layer "btm_hole_7" (solid, remove dead copper, pour order 29): 378.225,95.825 378.15,95.89 378.15,106.826 378.15,106.976 380.1,108.656 380.5,109 389.575,109 389.575,98.602 388.575,97.741
NetC96_2 on Bottom Layer "btm_hole_6" (solid, remove dead copper, pour order 23): 341.1,85.7 341.1,87.575 346.675,93.15 346.725,93.2 353.625,93.2 354.45,93.2 359.65,88 359.7,87.95 359.7,84.5
NetC95_2 on Bottom Layer "btm_hole_5" (solid, remove dead copper, pour order 21): 308.05,109.85 319.925,109.85 322.375,107.4 322.5,107.275 322.5,97.95 322.5,97.775 319.875,95.15 317.45,97.575 309.075,97.575
NetC94_2 on Bottom Layer "btm_hole_4" (solid, remove dead copper, pour order 15): 299.675,144.85 304.325,144.85 305.775,143.4 306.375,142.8 306.375,134.75 306.375,133.45 304.575,131.65 304.2,131.275 296.425,131.275 296.425,143.5 297.125,144.2
NetC93_2 on Bottom Layer "btm_hole_3" (solid, remove dead copper, pour order 14): 308.05,165.175 315.95,165.175 321.725,170.95 321.7,170.975 321.7,179.925 312.025,179.925 306.8,174.7
NetC92_2 on Bottom Layer "btm_hole_2" (solid, remove dead copper, pour order 8): 342.95,189.775 342.95,183.525 342.95,183.375 345.817,181.475 345.93,181.4 353.21,181.4 353.436,181.4 355.397,182.7 355.85,183 355.85,188.075 355.85,189.575 355.133,190.05
NetC91_2 on Bottom Layer "btm_hole_1" (solid, remove dead copper, pour order 6): 376.875,179.975 376.875,169.3 376.9,169.3 379.7,166.5 380,166.2 389.775,166.2 389.775,174.85 389.725,174.9

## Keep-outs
Keep-Out Layer:
  lines w0.2: 387.048,104.68 387.048,170.379
  lines w0.254: 300.45,140.396 ccw(c302.3,137.425) 300.47,134.442 ; 300.483,140.397 cw(c349.925,137.55) 312.775,170.3 ; 300.498,134.443 ccw(c349.925,137.55) 312.871,104.692 ; 312.77,170.304 cw(c316.2,171) 316.923,174.424 ; 312.836,104.701 ccw(c316.225,103.825) 317.127,100.443 ; 316.92,174.428 cw(c349.941,137.519) 346.92,186.951 ; 317.121,100.467 ccw(c350.02,137.484) 347.047,88.049 ; 346.969,186.984 cw(c349.8,184.925) 352.606,187.017 ; 347.048,88.071 ccw(c349.9,90.1) 352.789,88.124 ; 352.605,187.002 cw(c349.925,137.55) 382.905,174.496 ; 352.79,88.104 ccw(c349.983,137.549) 382.736,100.402 ; 382.728,100.41 ccw(c383.375,103.85) 386.815,104.495 ; 382.902,174.493 cw(c383.375,171.025) 386.847,170.581 ; 386.801,104.492 ccw(c349.925,137.55) 387.063,104.787 ; 386.835,170.57 cw(c349.925,137.55) 387.063,170.313

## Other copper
Top Layer:
  region net NetC72_1: 367.26,181.946 369.104,180.881 369.669,181.86 367.825,182.925
  rectangle net 5V: 358.275,162.725 365.4,164
  rectangle net A_GND: 350.4,102.325 354.95,103.675
  rectangle net A_GND: 353.3,100.6 354.95,103.425
  rectangle net A_GND: 353.375,110.8 354.875,114.275
  rectangle net A_GND: 350.325,112.575 354.875,114.275
  rectangle net A_GND: 350.375,122.675 354.8,124.475
  rectangle net A_GND: 353.325,120.9 355.05,124.475
  rectangle net VIN: 370.65,132.3 383.125,137.85
  rectangle net VIN: 367.975,95.45 375.475,145
  rectangle net VIN: 367.975,144.425 383.025,149.55
  rectangle net SEN_3_RAW: 350.4,96.1 354.525,98.95
  rectangle net W_COIL: 355.625,94.725 366.4,98.325
  rectangle net V_COIL: 357.325,105.975 366.425,109.45
  rectangle net U_COIL: 356.9,115.8 366.45,119.175
  rectangle net A_GND: 360.425,129.45 364.7,145.6
  region net A_GND: 365.1,155.75 365.1,150.45 376.575,150.45 376.575,155.75
  rectangle net SEN_2_RAW: 350.475,106.225 354.6,109.075
  rectangle net SEN_1_RAW: 350.475,116.3 354.6,119.15
  rectangle net W_COIL: 355.3,93.7 362.525,103.45
  rectangle net V_COIL: 355.3,104.2 362.525,113.95
  rectangle net U_COIL: 355.275,114.7 362.5,124.45
  rectangle net W_COIL: 379.5,114.725 384.725,119.7
  rectangle net V_COIL: 379.125,120.4 384.7,124.85
  rectangle net U_COIL: 378.975,125.825 384.675,129.775
  rectangle net A_GND: 363.6,167.875 366.525,181.675
  rectangle net NetC72_1: 354.65,178.95 361.525,182.9
  rectangle net NetC72_1: 354.65,182.05 367.825,182.925
  rectangle net NetC72_1: 367.2,177.25 369.075,182.125
  rectangle net 15V: 366.85,175.95 370.35,176.75
  rectangle net A_GND: 365.925,174.5 372.5,175.35
  rectangle net 5V: 357.725,168.675 360,175.25
  rectangle net 5V: 358.275,162.825 360,169.5
  rectangle net A_GND: 359.775,153.1 366.35,155.7
  rectangle net A_GND: 372.875,158.4 377.95,160.45
  rectangle net VIN: 374.35,163.55 384.525,165.1
  rectangle net VIN: 382.575,157.6 384.55,165.1
  rectangle net A_GND: 359.775,143.425 362.275,155.575
  rectangle net VIN: 377.925,155.925 386.175,156.975
  rectangle net VIN: 377.925,149.225 378.9,156.975
  rectangle net 15V: 361.025,159.825 367.45,162.175
  rectangle net NetC72_2: 359.9,177.275 363,178.375
  rectangle net VIN: 382.575,157.6 386.2,158.75
GND:
  rectangle net A_GND: 378.175,150.575 386.725,154.725
  rectangle net A_GND: 383.7,131.7 386.725,154.725
  rectangle net A_GND: 360.35,131.525 364.7,143.425
  rectangle net V_COIL: 379.225,120.4 384.625,124.75
  rectangle net U_COIL: 378.9,125.8 384.875,129.825
  rectangle net VIN: 367.975,95.45 375.45,148.575
  rectangle net VIN: 367.975,144.45 383,149.55
  rectangle net VIN: 368.975,132.425 383.1,137.825
  rectangle net A_GND: 385.25,112.35 386.725,132.85
VDD:
  rectangle net U_COIL: 355.5,115.1 362.5,124.025
  rectangle net V_COIL: 355.625,105.95 366.575,109.925
  rectangle net V_COIL: 355.5,105.275 362.575,113.15
  rectangle net W_COIL: 355.575,94.25 366.4,98.275
  rectangle net W_COIL: 355.575,95.625 362.525,102.5
  rectangle net A_GND: 360.45,138.5 386.725,143.45
  rectangle net A_GND: 383.05,138.5 386.725,154.725
  rectangle net A_GND: 378.125,150.525 386.725,154.725
  rectangle net A_GND: 360.45,129.525 364.625,143.45
Bottom Layer:
  rectangle net A_GND: 378.175,138.525 386.225,143.4
  rectangle net A_GND: 383.95,138.525 386.7,154.75
  rectangle net A_GND: 378.175,150.625 386.225,154.725
  region net A_GND: 365.45,161.2 365.45,154.275 376.25,154.275 376.25,161.2
  rectangle net SEN_3_RAW: 350.4,96.1 354.525,98.95
  rectangle net SEN_1_RAW: 350.475,116.3 354.6,119.15
  rectangle net SEN_2_RAW: 350.475,106.225 354.6,109.075
  rectangle net W_COIL: 379.525,114.725 384.7,119.7
  rectangle net V_COIL: 379.025,120.4 384.725,124.85
  rectangle net U_COIL: 379,125.825 384.725,129.85
  rectangle net U_COIL: 380.3,125.85 383.275,129.5
  region net 3V3_A_GND: 365.4,174.8 365.4,180.825 363.4,180.825 363.4,174.8
  region net 5V: 365.275,162.75 365.275,171.25 363.375,171.25 363.375,162.75
  rectangle net A_GND: 360.35,138.525 386.725,143.425
  rectangle net U_COIL: 360,114.8 362.425,124.4
  rectangle net V_COIL: 359.925,104.275 362.375,113.85
  rectangle net W_COIL: 359.925,93.85 362.4,103.3

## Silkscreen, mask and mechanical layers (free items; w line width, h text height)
Top Overlay:
  text "5V" at 346.6,177.175 h1.5
  text "15V" at 349.925,177.15 h1.5
  text "3V3" at 342.525,177.125 h1.5
  text "BLINK" at 338.6,177.1 h1.5
  text "sig2-" at 311.225,165.15 h1
  text "A" at 348.775,164.8 h1
  text "I" at 354.3,164.775 h1
  text "5V" at 345.925,164.75 h1
  text "B" at 351.475,164.75 h1
  text "GND" at 355.725,164.75 h1
  text "sig2+" at 311,160.3 h1
  text "GND" at 310.2,158.075 h1
  text "sig1-" at 309.075,155.9 h1
  text "5V" at 345.875,154.4 h1
  text "A" at 348.65,154.4 h1
  text "B" at 351.4,154.375 h1
  text "C" at 353.925,154.375 h1
  text "GND" at 355.75,154.35 h1
  text "sig1+" at 307.975,153.7 h1
  text "-" at 375.3,153 h2
  text "5V" at 307.05,151.325 h1
  text "A" at 355.05,147.775 h2
  text "L" at 348.725,147.725 h2
  text "B" at 352.65,147.725 h2
  text "H" at 346,147.675 h2
  text "+" at 375.225,144.9 h2
  text "-" at 375.475,140.35 h2
  text "+" at 375.25,135.066 h1
  text "+" at 375.275,133.1 h2
  text "U" at 375.15,126.85 h2
  text "V" at 375.2,121.925 h2
  text "W" at 374.675,117.175 h2
Top Paste:
  region: 365.1,155.75 365.1,150.45 376.575,150.45 376.575,155.75
  rectangle: 355.575,94.175 362.35,103.025
  rectangle: 368.375,95.525 375.15,103.525
  rectangle: 355.55,104.65 362.325,113.5
  rectangle: 355.55,115.2 362.325,124.05
  rectangle: 368.3,104.875 375.075,112.875
  rectangle: 368.275,115.425 375.05,123.425
Top Solder:
  rectangle: 368.625,96.625 374.675,149.275
Bottom Solder:
  rectangle: 360.125,114.95 362.325,124.275
  rectangle: 360.075,104.375 362.325,113.75
  rectangle: 360,93.925 362.4,103.3
  rectangle: 374.225,125.975 383.475,129.6
  rectangle: 362.25,115.7 365.525,119.375
  rectangle: 362.275,106.3 369.35,109.95
  rectangle: 362.3,94.5 368.35,98.125
  rectangle: 379.8,109.975 383.7,119.35
  rectangle: 378.1,120.5 383.7,124.6
  rectangle: 372.325,112.75 375.925,118.8
  region: 365.57,115.653 376.791,126.858 374.146,129.506 362.925,118.302
  region: 369.388,106.262 375.9,112.775 373.262,115.413 366.75,108.9
  region: 374.988,116.137 380.763,121.913 378.125,124.55 372.35,118.775
  region: 368.356,94.542 383.742,109.907 381.301,112.351 365.915,96.986
  rectangle: 383.957,138.5 386.707,154.725
  rectangle: 360.357,138.5 386.732,143.4
  rectangle: 378.825,150.5 386.707,154.725
  lines w4: 352.15,102.775 355.518,102.775 357.101,104.358 357.101,111.017 355.268,112.85 352.15,112.85 ; 352.181,122.892 353.474,122.892 362.307,131.725 362.307,141.075 ; 354.415,122.892 357.232,120.075 357.232,114.75 355.299,112.817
